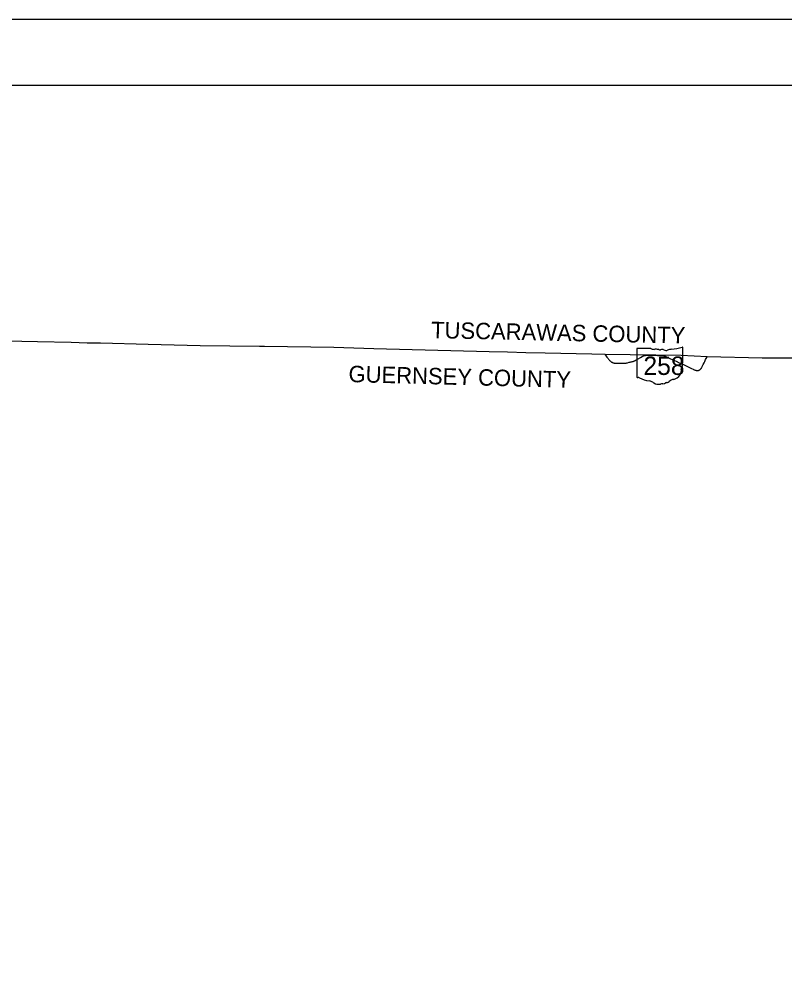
# Model space of a CAD drawing. Extents: x 1913970 to 2397567, y 78841 to 829347.
# Drawn here: x 2236793 to 2283311, y 770418 to 829347 of the extents above; entities that cross this region are included whole.
import ezdxf

# ---------------------------------------------------------------- set-up
doc = ezdxf.new("R2010")
doc.units = 0
for name, color, linetype in [('GM_X_County', 7, 'Continuous'), ('GM_X_County_Text', 7, 'Continuous'), ('GM_X_State_Location', 7, 'Continuous'), ('GM_X_State_Route', 7, 'Continuous'), ('GM_X_State_Shield', 7, 'Continuous'), ('SH_Border', 7, 'Continuous'), ('SH_Cut_Line', 7, 'Continuous')]:
    doc.layers.add(name, color=color, linetype=linetype)

msp = doc.modelspace()

# ---------------------------------------------------------------- linework, layer by layer
at = {"layer": 'GM_X_County'}
msp.add_lwpolyline([(2235020, 809833), (2237884, 809769), (2239931, 809724), (2240903, 809689), (2241728, 809679), (2244624, 809598), (2247788, 809512), (2251387, 809474), (2251688, 809476), (2255912, 809422), (2258347, 809341), (2265356, 809149), (2266459, 809132), (2267588, 809088), (2268763, 809075), (2271582, 809019), (2272387, 808998), (2277016, 808932), (2278609, 808858), (2281956, 808767), (2284041, 808770)], dxfattribs=at)
at = {"layer": 'GM_X_State_Route'}
for points in [[(2272388, 808995), (2272431, 808928), (2272470, 808872), (2272510, 808814), (2272537, 808777), (2272556, 808752), (2272576, 808725), (2272598, 808696), (2272622, 808668), (2272646, 808641), (2272669, 808616), (2272702, 808583), (2272726, 808562), (2272747, 808545), (2272768, 808530), (2272794, 808514), (2272821, 808498), (2272846, 808486), (2272872, 808475), (2272897, 808467), (2272922, 808459), (2272949, 808452), (2272977, 808448), (2273002, 808445), (2273035, 808443), (2273154, 808445), (2273272, 808443), (2273390, 808440), (2273472, 808439), (2273512, 808438), (2273549, 808439), (2273582, 808442), (2273611, 808445), (2273635, 808448), (2273673, 808455), (2273711, 808463), (2273757, 808474), (2273858, 808500), (2273920, 808514), (2273966, 808524), (2274011, 808534), (2274045, 808541), (2274071, 808547), (2274103, 808556), (2274129, 808564), (2274161, 808575), (2274183, 808583), (2274218, 808599), (2274252, 808616), (2274294, 808639), (2274400, 808701), (2274559, 808799), (2274642, 808847), (2274695, 808876), (2274720, 808888), (2274732, 808892), (2274743, 808897)], [(2274743, 808897), (2274766, 808904), (2274792, 808910), (2274815, 808915), (2274837, 808918), (2274861, 808921), (2274884, 808922), (2274906, 808922), (2275046, 808922), (2275466, 808922), (2275593, 808921), (2275671, 808920), (2275751, 808917), (2275824, 808915), (2275852, 808913), (2275879, 808911), (2275902, 808908), (2275924, 808905), (2275943, 808901)], [(2275943, 808901), (2275959, 808897), (2275980, 808892), (2276004, 808885), (2276022, 808879), (2276044, 808870), (2276068, 808860), (2276094, 808849), (2276127, 808833), (2276171, 808812), (2276328, 808738), (2276514, 808651), (2276721, 808558), (2276907, 808473), (2277035, 808415), (2277276, 808302), (2277642, 808125), (2277749, 808075), (2277776, 808063), (2277809, 808049), (2277842, 808036), (2277865, 808027), (2277890, 808018), (2277916, 808010), (2277936, 808005), (2277955, 808002), (2277977, 808000), (2277998, 807998), (2278021, 807998), (2278041, 808000), (2278063, 808003), (2278075, 808006), (2278096, 808013), (2278115, 808021), (2278131, 808031), (2278154, 808046), (2278181, 808067), (2278198, 808083), (2278212, 808097), (2278227, 808114), (2278238, 808128), (2278251, 808145), (2278264, 808167), (2278278, 808193), (2278291, 808218), (2278306, 808247), (2278325, 808287), (2278367, 808371), (2278415, 808472), (2278456, 808555), (2278511, 808662), (2278573, 808783), (2278610, 808855)]]:
    msp.add_lwpolyline(points, dxfattribs=at)
at = {"layer": 'GM_X_State_Shield'}
for p, q in [((2274324, 809310), (2274324, 807609)), ((2275172, 809340), (2274352, 809340)), ((2277126, 808492), (2277126, 809382)), ((2277126, 808492), (2277126, 808492))]:
    msp.add_line(p, q, dxfattribs=at)
for centre, major_axis, start_param, end_param in [((2274356, 809314), (32.5, 0), 1.712693, 3.28349), ((2275368, 809537), (315, 0), 4.042523, 4.731795), ((2275472, 808385), (1130, 0), 1.404758, 1.657858), ((2275729, 809323), (90.8, 0), 3.836095, 5.185415), ((2275862, 809126), (189, 0), 0.950623, 2.079405), ((2276106, 809396), (227, 0), 4.081561, 5.145723), ((2276507, 808820), (598, 0), 1.699011, 2.107814), ((2276128, 811659), (2971, 0), 4.814394, 5.042369), ((2277095, 809385), (31.2, 0), 6.141152, 7.989035), ((2276294, 808006), (743, 0), 5.101752, 6.440018), ((2277238, 808119), (211, 0), 2.387724, 3.262537), ((2277119, 808426), (48.3, 0), 1.883978, 3.671073), ((2276812, 808314), (290, 0), 5.934695, 6.695948), ((2277093, 808488), (33.4, 0), 5.05454, 6.418171), ((2274357, 807605), (32.7, 0), 3.00124, 4.508301), ((2274361, 807779), (250, 0), 4.665946, 4.897461), ((2274413, 807511), (90.1, 0), 0.519207, 1.627899), ((2275550, 809039), (2146, 0), 4.195997, 4.488961), ((2274911, 806845), (671, 0), 0.823519, 1.323587), ((2276092, 807444), (240, 0), 4.937069, 5.64225), ((2276608, 807132), (407, 0), 1.647645, 2.488434), ((2275637, 807503), (426, 0), 4.026481, 4.996735), ((2275883, 806914), (350, 0), 1.495662, 1.94098), ((2275914, 807375), (227, 0), 4.691044, 5.507374), ((2276119, 807210), (63.9, 0), 1.147584, 2.315152)]:
    msp.add_ellipse(centre, major_axis=major_axis, ratio=0.8, start_param=start_param, end_param=end_param, dxfattribs=at)
at = {"layer": 'SH_Border'}
msp.add_lwpolyline([(2137567, 825347), (2393567, 825347), (2393567, 657347), (2137567, 657347)], close=True, dxfattribs=at)
at = {"layer": 'SH_Cut_Line'}
msp.add_lwpolyline([(2125567, 653347), (2397567, 653347), (2397567, 829347), (2125567, 829347)], close=True, dxfattribs=at)

# ---------------------------------------------------------------- texts
at = {"layer": 'GM_X_County_Text'}
for s, rotation, p in [('TUSCARAWAS COUNTY', 358.76344, (2261815, 809968)), ('GUERNSEY COUNTY', 358.48143, (2256791, 807297))]:
    msp.add_text(s, height=1000, rotation=rotation, dxfattribs=at).set_placement(p)
at = {"layer": 'GM_X_State_Location'}
msp.add_text('258', height=1, rotation=0.00001, dxfattribs=at).set_placement((2275319, 808730))
for s in ['s', 'r']:
    msp.add_text(s, height=1, dxfattribs=at).set_placement((2275672, 808803))
at = {"layer": 'GM_X_State_Shield'}
msp.add_text('258', height=1120.7, dxfattribs=at).set_placement((2274729, 807729))

doc.saveas('drawing.dxf')
